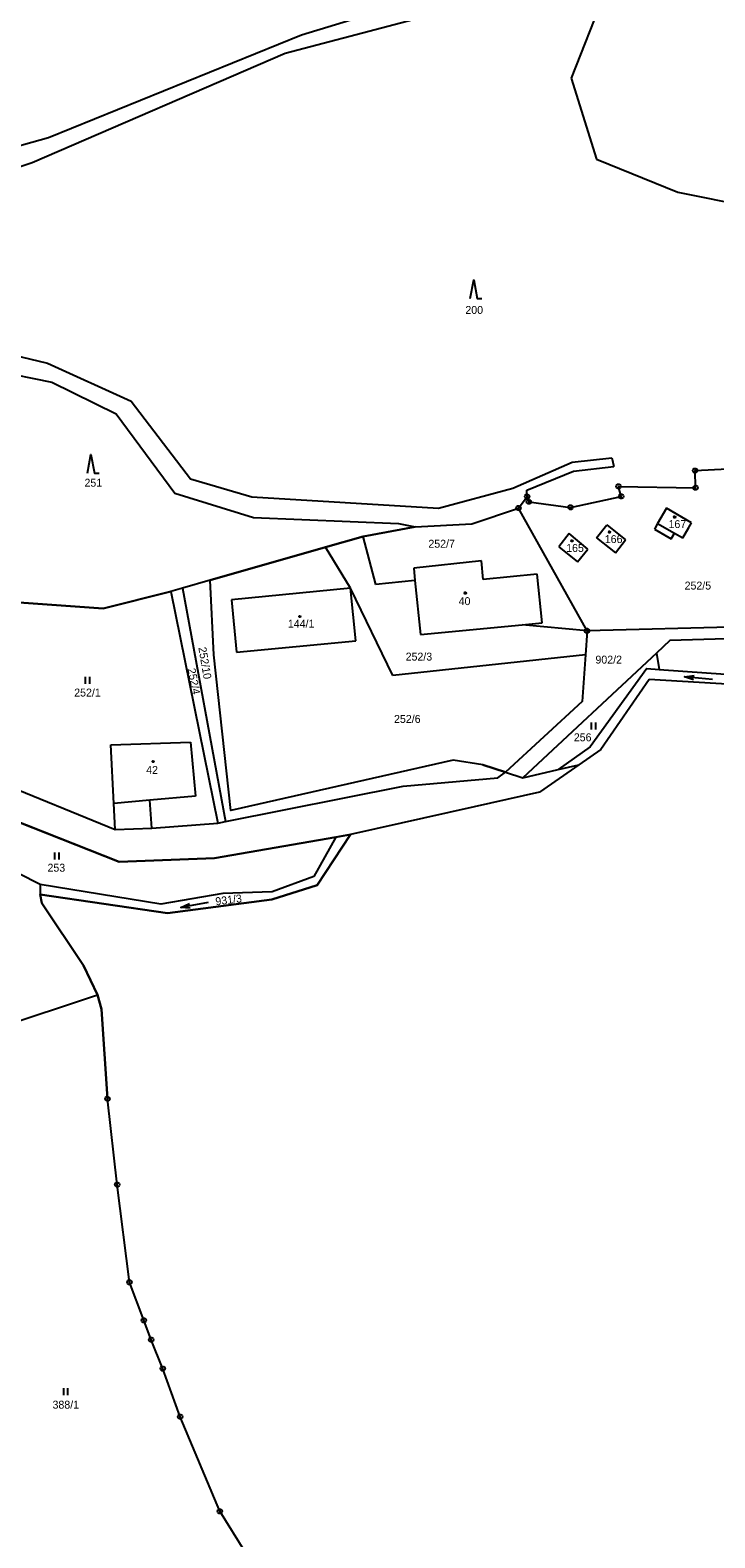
# Model space of a CAD drawing. Extents: x -580551 to -575069, y -1073031 to -1067931.
# Drawn here: x -577069.2 to -576922.3, y -1070091.5 to -1069768.1 of the extents above; entities that cross this region are included whole.
import ezdxf

# ---------------------------------------------------------------- set-up
doc = ezdxf.new("R2010")
doc.units = 0
for name, color, linetype in [('Druh pozemku', 7, 'Continuous'), ('Geodetické body', 7, 'Continuous'), ('Katastrální hranice', 7, 'Continuous'), ('Parcela', 7, 'Continuous'), ('Parcelní číslo', 7, 'Continuous'), ('Parcelní číslo_stavba', 7, 'Continuous'), ('SR - hranice státu', 7, 'Continuous'), ('SR - vnitřní hranice', 7, 'Continuous'), ('Vnitřní kresba', 7, 'Continuous'), ('Vrstva 6', 7, 'Continuous')]:
    doc.layers.add(name, color=color, linetype=linetype)

msp = doc.modelspace()

# ---------------------------------------------------------------- linework, layer by layer
at = {"layer": 'Druh pozemku'}
for p, q in [((-577057.43, -1069906.84), (-577057.43, -1069908.34)), ((-577056.43, -1069908.34), (-577056.43, -1069906.84)), ((-576922.843, -1069907.4), (-576928.817, -1069906.84)), ((-576948.87, -1069916.65), (-576948.87, -1069918.15)), ((-576947.87, -1069918.15), (-576947.87, -1069916.65)), ((-577063.95, -1069944.52), (-577063.95, -1069946.02)), ((-577062.95, -1069946.02), (-577062.95, -1069944.52)), ((-577030.998, -1069955.278), (-577036.902, -1069956.342)), ((-577062.09, -1070059.4), (-577062.09, -1070060.9)), ((-577061.09, -1070060.9), (-577061.09, -1070059.4))]:
    msp.add_line(p, q, dxfattribs=at)
for points in [[(-576974.79, -1069825.67), (-576974.04, -1069821.67), (-576973.29, -1069825.67), (-576972.29, -1069825.67)], [(-577056.93, -1069863.15), (-577056.18, -1069859.15), (-577055.43, -1069863.15), (-577054.43, -1069863.15)], [(-576926.872, -1069907.524), (-576928.817, -1069906.84), (-576926.779, -1069906.529)], [(-577034.845, -1069956.48), (-577036.902, -1069956.342), (-577035.023, -1069955.495)]]:
    msp.add_lwpolyline(points, dxfattribs=at)
for points in [[(-576930.83, -1069872.42), (-576930.74, -1069872.57), (-576930.83, -1069872.72), (-576931.01, -1069872.72), (-576931.1, -1069872.57), (-576931.01, -1069872.42)], [(-576952.88, -1069877.5), (-576952.79, -1069877.65), (-576952.88, -1069877.8), (-576953.06, -1069877.8), (-576953.15, -1069877.65), (-576953.06, -1069877.5)], [(-576944.82, -1069875.63), (-576944.73, -1069875.78), (-576944.82, -1069875.93), (-576945, -1069875.93), (-576945.09, -1069875.78), (-576945, -1069875.63)], [(-576975.75, -1069888.71), (-576975.66, -1069888.86), (-576975.75, -1069889.01), (-576975.93, -1069889.01), (-576976.02, -1069888.86), (-576975.93, -1069888.71)], [(-577011.27, -1069893.78), (-577011.18, -1069893.93), (-577011.27, -1069894.08), (-577011.45, -1069894.08), (-577011.54, -1069893.93), (-577011.45, -1069893.78)], [(-577042.74, -1069924.85), (-577042.65, -1069925), (-577042.74, -1069925.15), (-577042.92, -1069925.15), (-577043.01, -1069925), (-577042.92, -1069924.85)]]:
    msp.add_lwpolyline(points, close=True, dxfattribs=at)
at = {"layer": 'Geodetické body'}
for p, q in [((-576926.68, -1069862.61), (-576926.44, -1069862.61)), ((-576962.71, -1069868.15), (-576962.47, -1069868.15)), ((-576943.1, -1069866), (-576942.86, -1069866)), ((-576942.52, -1069868.15), (-576942.28, -1069868.15)), ((-576926.57, -1069866.31), (-576926.33, -1069866.31)), ((-576964.57, -1069870.66), (-576964.33, -1069870.66)), ((-576962.35, -1069869.31), (-576962.11, -1069869.31)), ((-576953.38, -1069870.49), (-576953.14, -1069870.49)), ((-576949.86, -1069896.96), (-576949.62, -1069896.96)), ((-577052.75, -1069997.36), (-577052.51, -1069997.36)), ((-577050.64, -1070015.78), (-577050.4, -1070015.78)), ((-577048.03, -1070036.7), (-577047.79, -1070036.7)), ((-577044.94, -1070044.86), (-577044.7, -1070044.86)), ((-577043.37, -1070049.05), (-577043.13, -1070049.05)), ((-577040.89, -1070055.25), (-577040.65, -1070055.25)), ((-577037.13, -1070065.58), (-577036.89, -1070065.58)), ((-577028.64, -1070085.83), (-577028.4, -1070085.83))]:
    msp.add_line(p, q, dxfattribs=at)
for points in [[(-576926.41, -1069862.13), (-576926.16, -1069862.31), (-576926.06, -1069862.6), (-576926.16, -1069862.89), (-576926.41, -1069863.07), (-576926.72, -1069863.07), (-576926.97, -1069862.89), (-576927.07, -1069862.6), (-576926.97, -1069862.31), (-576926.72, -1069862.13)], [(-576962.44, -1069867.67), (-576962.19, -1069867.85), (-576962.09, -1069868.14), (-576962.19, -1069868.43), (-576962.44, -1069868.61), (-576962.75, -1069868.61), (-576963, -1069868.43), (-576963.1, -1069868.14), (-576963, -1069867.85), (-576962.75, -1069867.67)], [(-576942.83, -1069865.52), (-576942.58, -1069865.7), (-576942.48, -1069865.99), (-576942.58, -1069866.28), (-576942.83, -1069866.46), (-576943.14, -1069866.46), (-576943.39, -1069866.28), (-576943.49, -1069865.99), (-576943.39, -1069865.7), (-576943.14, -1069865.52)], [(-576942.25, -1069867.67), (-576942, -1069867.85), (-576941.9, -1069868.14), (-576942, -1069868.43), (-576942.25, -1069868.61), (-576942.56, -1069868.61), (-576942.81, -1069868.43), (-576942.91, -1069868.14), (-576942.81, -1069867.85), (-576942.56, -1069867.67)], [(-576926.3, -1069865.83), (-576926.05, -1069866.01), (-576925.95, -1069866.3), (-576926.05, -1069866.59), (-576926.3, -1069866.77), (-576926.61, -1069866.77), (-576926.86, -1069866.59), (-576926.96, -1069866.3), (-576926.86, -1069866.01), (-576926.61, -1069865.83)], [(-576964.3, -1069870.18), (-576964.05, -1069870.36), (-576963.95, -1069870.65), (-576964.05, -1069870.94), (-576964.3, -1069871.12), (-576964.61, -1069871.12), (-576964.86, -1069870.94), (-576964.96, -1069870.65), (-576964.86, -1069870.36), (-576964.61, -1069870.18)], [(-576962.08, -1069868.83), (-576961.83, -1069869.01), (-576961.73, -1069869.3), (-576961.83, -1069869.59), (-576962.08, -1069869.77), (-576962.39, -1069869.77), (-576962.64, -1069869.59), (-576962.74, -1069869.3), (-576962.64, -1069869.01), (-576962.39, -1069868.83)], [(-576953.11, -1069870.01), (-576952.86, -1069870.19), (-576952.76, -1069870.48), (-576952.86, -1069870.77), (-576953.11, -1069870.95), (-576953.42, -1069870.95), (-576953.67, -1069870.77), (-576953.77, -1069870.48), (-576953.67, -1069870.19), (-576953.42, -1069870.01)], [(-576949.59, -1069896.48), (-576949.34, -1069896.66), (-576949.24, -1069896.95), (-576949.34, -1069897.24), (-576949.59, -1069897.42), (-576949.9, -1069897.42), (-576950.15, -1069897.24), (-576950.25, -1069896.95), (-576950.15, -1069896.66), (-576949.9, -1069896.48)], [(-577052.48, -1069996.88), (-577052.23, -1069997.06), (-577052.13, -1069997.35), (-577052.23, -1069997.64), (-577052.48, -1069997.82), (-577052.79, -1069997.82), (-577053.04, -1069997.64), (-577053.14, -1069997.35), (-577053.04, -1069997.06), (-577052.79, -1069996.88)], [(-577050.37, -1070015.3), (-577050.12, -1070015.48), (-577050.02, -1070015.77), (-577050.12, -1070016.06), (-577050.37, -1070016.24), (-577050.68, -1070016.24), (-577050.93, -1070016.06), (-577051.03, -1070015.77), (-577050.93, -1070015.48), (-577050.68, -1070015.3)], [(-577047.76, -1070036.22), (-577047.51, -1070036.4), (-577047.41, -1070036.69), (-577047.51, -1070036.98), (-577047.76, -1070037.16), (-577048.07, -1070037.16), (-577048.32, -1070036.98), (-577048.42, -1070036.69), (-577048.32, -1070036.4), (-577048.07, -1070036.22)], [(-577044.67, -1070044.38), (-577044.42, -1070044.56), (-577044.32, -1070044.85), (-577044.42, -1070045.14), (-577044.67, -1070045.32), (-577044.98, -1070045.32), (-577045.23, -1070045.14), (-577045.33, -1070044.85), (-577045.23, -1070044.56), (-577044.98, -1070044.38)], [(-577043.1, -1070048.57), (-577042.85, -1070048.75), (-577042.75, -1070049.04), (-577042.85, -1070049.33), (-577043.1, -1070049.51), (-577043.41, -1070049.51), (-577043.66, -1070049.33), (-577043.76, -1070049.04), (-577043.66, -1070048.75), (-577043.41, -1070048.57)], [(-577040.62, -1070054.77), (-577040.37, -1070054.95), (-577040.27, -1070055.24), (-577040.37, -1070055.53), (-577040.62, -1070055.71), (-577040.93, -1070055.71), (-577041.18, -1070055.53), (-577041.28, -1070055.24), (-577041.18, -1070054.95), (-577040.93, -1070054.77)], [(-577036.86, -1070065.1), (-577036.61, -1070065.28), (-577036.51, -1070065.57), (-577036.61, -1070065.86), (-577036.86, -1070066.04), (-577037.17, -1070066.04), (-577037.42, -1070065.86), (-577037.52, -1070065.57), (-577037.42, -1070065.28), (-577037.17, -1070065.1)], [(-577028.37, -1070085.35), (-577028.12, -1070085.53), (-577028.02, -1070085.82), (-577028.12, -1070086.11), (-577028.37, -1070086.29), (-577028.68, -1070086.29), (-577028.93, -1070086.11), (-577029.03, -1070085.82), (-577028.93, -1070085.53), (-577028.68, -1070085.35)]]:
    msp.add_lwpolyline(points, close=True, dxfattribs=at)
at = {"layer": 'Katastrální hranice'}
for p, q in [((-576936.44, -1069907.45), (-576946.78, -1069922.44)), ((-576902.47, -1069909.45), (-576936.44, -1069907.45)), ((-576946.78, -1069922.44), (-576951.48, -1069925.7)), ((-576951.48, -1069925.7), (-576959.97, -1069931.59)), ((-576959.97, -1069931.59), (-576973.92, -1069934.75)), ((-576973.92, -1069934.75), (-577000.48, -1069940.66)), ((-577000.48, -1069940.66), (-577007.65, -1069951.52)), ((-577007.65, -1069951.52), (-577017.38, -1069954.6)), ((-577039.74, -1069957.53), (-577067.05, -1069953.57)), ((-577067.05, -1069953.57), (-577066.7, -1069955.43)), ((-577066.7, -1069955.43), (-577057.78, -1069968.74)), ((-577017.38, -1069954.6), (-577039.74, -1069957.53)), ((-577057.78, -1069968.74), (-577054.76, -1069975.04)), ((-577054.76, -1069975.04), (-577053.89, -1069978.15)), ((-577053.89, -1069978.15), (-577052.63, -1069997.36)), ((-577050.52, -1070015.78), (-577052.63, -1069997.36)), ((-577047.91, -1070036.7), (-577050.52, -1070015.78)), ((-577044.82, -1070044.86), (-577047.91, -1070036.7)), ((-577043.25, -1070049.05), (-577044.82, -1070044.86)), ((-577040.77, -1070055.25), (-577043.25, -1070049.05)), ((-577037.01, -1070065.58), (-577040.77, -1070055.25)), ((-577028.52, -1070085.83), (-577037.01, -1070065.58)), ((-577023.03, -1070094.68), (-577028.52, -1070085.83))]:
    msp.add_line(p, q, dxfattribs=at)
at = {"layer": 'Parcela'}
for p, q in [((-576944.69, -1069748.96), (-577011, -1069769.24)), ((-576943.71, -1069754.47), (-577014.5, -1069773.16)), ((-576943.71, -1069754.47), (-576953.12, -1069778.4)), ((-577011, -1069769.24), (-577065.27, -1069791.23)), ((-577014.5, -1069773.16), (-577068.75, -1069796.56)), ((-576953.12, -1069778.4), (-576947.74, -1069795.79)), ((-577065.27, -1069791.23), (-577099.61, -1069800.79)), ((-577068.75, -1069796.56), (-577096.37, -1069805.82)), ((-576947.74, -1069795.79), (-576930.27, -1069802.9)), ((-576930.27, -1069802.9), (-576890.62, -1069810.92)), ((-577084.11, -1069835.17), (-577065.48, -1069839.55)), ((-577082.96, -1069839.91), (-577064.57, -1069843.63)), ((-577065.48, -1069839.55), (-577047.56, -1069847.69)), ((-577064.57, -1069843.63), (-577050.77, -1069850.42)), ((-577047.56, -1069847.69), (-577034.81, -1069864.39)), ((-577050.77, -1069850.42), (-577038.16, -1069867.46)), ((-576965.63, -1069866.39), (-576952.96, -1069860.79)), ((-576952.96, -1069860.79), (-576944.41, -1069859.85)), ((-576952.63, -1069862.75), (-576943.96, -1069861.75)), ((-576944.41, -1069859.85), (-576943.96, -1069861.75)), ((-576926.56, -1069862.61), (-576916.84, -1069862.07)), ((-577034.81, -1069864.39), (-577021.65, -1069868.22)), ((-576962.63, -1069866.84), (-576952.63, -1069862.75)), ((-576926.45, -1069866.31), (-576926.56, -1069862.61)), ((-577038.16, -1069867.46), (-577021.28, -1069872.69)), ((-577021.65, -1069868.22), (-576981.62, -1069870.67)), ((-576981.62, -1069870.67), (-576965.63, -1069866.39)), ((-576964.45, -1069870.66), (-576962.59, -1069868.15)), ((-576962.59, -1069868.15), (-576962.63, -1069866.84)), ((-576962.59, -1069868.15), (-576962.23, -1069869.31)), ((-576953.26, -1069870.49), (-576942.4, -1069868.15)), ((-576942.4, -1069868.15), (-576942.98, -1069866)), ((-576942.98, -1069866), (-576926.45, -1069866.31)), ((-576974.48, -1069874.01), (-576964.45, -1069870.66)), ((-576949.74, -1069896.96), (-576964.45, -1069870.66)), ((-576962.23, -1069869.31), (-576953.26, -1069870.49)), ((-576932.67, -1069870.66), (-576934.59, -1069873.93)), ((-576927.31, -1069873.82), (-576932.67, -1069870.66)), ((-577021.28, -1069872.69), (-576990.21, -1069873.93)), ((-576986.63, -1069874.69), (-576997.76, -1069876.76)), ((-576990.21, -1069873.93), (-576986.63, -1069874.69)), ((-576986.63, -1069874.69), (-576974.48, -1069874.01)), ((-576947.7, -1069877.04), (-576945.49, -1069874.25)), ((-576945.49, -1069874.25), (-576941.45, -1069877.47)), ((-576934.59, -1069873.93), (-576935.29, -1069875.14)), ((-576929.22, -1069877.06), (-576927.89, -1069874.8)), ((-576927.89, -1069874.8), (-576927.31, -1069873.82)), ((-576997.76, -1069876.76), (-577005.86, -1069879.06)), ((-576995.04, -1069887.02), (-576997.76, -1069876.76)), ((-576953.56, -1069876.13), (-576955.81, -1069878.97)), ((-576949.55, -1069879.44), (-576953.56, -1069876.13)), ((-576947.7, -1069877.04), (-576943.66, -1069880.24)), ((-576943.66, -1069880.24), (-576941.45, -1069877.47)), ((-576935.29, -1069875.14), (-576931.69, -1069877.22)), ((-576931.69, -1069877.22), (-576931, -1069876.03)), ((-576931, -1069876.03), (-576929.22, -1069877.06)), ((-577005.86, -1069879.06), (-577030.61, -1069886.1)), ((-577000.5, -1069887.82), (-577005.86, -1069879.06)), ((-576955.81, -1069878.97), (-576951.79, -1069882.15)), ((-576951.79, -1069882.15), (-576949.55, -1069879.44)), ((-576972.39, -1069881.95), (-576986.91, -1069883.57)), ((-576986.91, -1069883.57), (-576986.65, -1069886.16)), ((-576972, -1069885.97), (-576972.39, -1069881.95)), ((-577036.54, -1069887.81), (-577039.02, -1069888.52)), ((-577030.61, -1069886.1), (-577036.54, -1069887.81)), ((-577029.78, -1069902.1), (-577030.61, -1069886.1)), ((-577000.5, -1069887.82), (-577026, -1069890.35)), ((-576991.42, -1069906.59), (-577000.5, -1069887.82)), ((-576999.33, -1069899.12), (-577000.5, -1069887.82)), ((-576986.65, -1069886.16), (-576995.04, -1069887.02)), ((-576986.65, -1069886.16), (-576985.5, -1069897.77)), ((-576960.44, -1069884.83), (-576972, -1069885.97)), ((-576959.37, -1069895.25), (-576960.44, -1069884.83)), ((-577053.57, -1069892.18), (-577073.55, -1069890.78)), ((-577039.02, -1069888.52), (-577053.57, -1069892.18)), ((-577039.02, -1069888.52), (-577028.97, -1069938.24)), ((-577026, -1069890.35), (-577024.94, -1069901.53)), ((-576985.5, -1069897.77), (-576963.65, -1069895.66)), ((-576963.65, -1069895.66), (-576959.37, -1069895.25)), ((-576949.74, -1069896.96), (-576963.65, -1069895.66)), ((-576949.74, -1069896.96), (-576950.1, -1069902.15)), ((-576916.3, -1069896.13), (-576949.74, -1069896.96)), ((-577024.94, -1069901.53), (-576999.33, -1069899.12)), ((-576931.95, -1069899.07), (-576934.85, -1069901.78)), ((-576911.76, -1069898.43), (-576931.95, -1069899.07)), ((-577026.16, -1069935.55), (-577029.78, -1069902.1)), ((-576950.1, -1069902.15), (-576991.42, -1069906.59)), ((-576934.85, -1069901.78), (-576963.49, -1069928.49)), ((-576950.1, -1069902.15), (-576950.79, -1069912.11)), ((-576934.85, -1069901.78), (-576934.29, -1069905.26)), ((-576936.94, -1069905.08), (-576949.05, -1069921.87)), ((-576936.94, -1069905.08), (-576934.29, -1069905.26)), ((-576934.29, -1069905.26), (-576902.79, -1069907.45)), ((-576950.79, -1069912.11), (-576967.23, -1069927.27)), ((-577050.1, -1069946.52), (-577112.01, -1069922.1)), ((-577051.92, -1069921.46), (-577034.83, -1069920.88)), ((-577051.24, -1069934.01), (-577051.92, -1069921.46)), ((-577034.83, -1069920.88), (-577033.74, -1069932.43)), ((-576949.05, -1069921.87), (-576955.92, -1069926.73)), ((-577083.84, -1069926.22), (-577050.94, -1069939.56)), ((-576978.45, -1069924.69), (-577026.16, -1069935.55)), ((-576972.1, -1069925.69), (-576978.45, -1069924.69)), ((-576972.1, -1069925.69), (-576967.23, -1069927.27)), ((-576963.49, -1069928.49), (-576955.92, -1069926.73)), ((-576955.92, -1069926.73), (-576951.48, -1069925.7)), ((-577067.04, -1069951.41), (-577115.27, -1069927.04)), ((-576989.21, -1069930.32), (-576968.9, -1069928.52)), ((-576968.9, -1069928.52), (-576967.23, -1069927.27)), ((-576967.23, -1069927.27), (-576963.49, -1069928.49)), ((-577033.74, -1069932.43), (-577043.55, -1069933.31)), ((-577043.12, -1069939.33), (-577043.55, -1069933.31)), ((-577027.29, -1069937.91), (-576989.21, -1069930.32)), ((-577050.94, -1069939.56), (-577051.24, -1069934.01)), ((-577050.94, -1069939.56), (-577043.12, -1069939.33)), ((-577043.12, -1069939.33), (-577028.97, -1069938.24)), ((-577028.97, -1069938.24), (-577027.29, -1069937.91)), ((-577003.65, -1069941.21), (-577029.68, -1069945.77)), ((-577003.65, -1069941.21), (-577008.37, -1069949.65)), ((-577000.48, -1069940.66), (-577003.65, -1069941.21)), ((-577029.68, -1069945.77), (-577050.1, -1069946.52)), ((-577067.04, -1069951.41), (-577067.05, -1069953.57)), ((-577041.19, -1069955.62), (-577067.04, -1069951.41)), ((-577008.37, -1069949.65), (-577017.31, -1069952.95)), ((-577027.88, -1069953.34), (-577041.19, -1069955.62)), ((-577017.31, -1069952.95), (-577027.88, -1069953.34)), ((-577082.98, -1069984.46), (-577054.76, -1069975.04))]:
    msp.add_line(p, q, dxfattribs=at)
at = {"layer": 'SR - hranice státu'}
for p, q in [((-577073.55, -1069890.78), (-577053.57, -1069892.18)), ((-577053.57, -1069892.18), (-577039.02, -1069888.52))]:
    msp.add_line(p, q, dxfattribs=at)
for points in [[(-576942.98, -1069866), (-576926.45, -1069866.31), (-576926.56, -1069862.61), (-576916.84, -1069862.07), (-576916.77, -1069866.51), (-576900.43, -1069867.8)], [(-577005.86, -1069879.06), (-576997.76, -1069876.76), (-576986.63, -1069874.69), (-576974.48, -1069874.01), (-576964.45, -1069870.66), (-576962.59, -1069868.15), (-576962.23, -1069869.31), (-576953.26, -1069870.49), (-576942.4, -1069868.15), (-576942.98, -1069866)], [(-577039.02, -1069888.52), (-577028.97, -1069938.24), (-577027.29, -1069937.91), (-576989.21, -1069930.32), (-576968.9, -1069928.52), (-576967.23, -1069927.27), (-576972.1, -1069925.69), (-576978.45, -1069924.69), (-577026.16, -1069935.55), (-577029.78, -1069902.1), (-577030.61, -1069886.1), (-577005.86, -1069879.06)], [(-577112.01, -1069922.1), (-577050.1, -1069946.52), (-577029.68, -1069945.77), (-577003.65, -1069941.21), (-577000.48, -1069940.66)]]:
    msp.add_lwpolyline(points, dxfattribs=at)
at = {"layer": 'SR - vnitřní hranice'}
msp.add_lwpolyline([(-577023.03, -1070094.68), (-577028.52, -1070085.83), (-577037.01, -1070065.58), (-577040.77, -1070055.25), (-577043.25, -1070049.05), (-577044.82, -1070044.86), (-577047.91, -1070036.7), (-577050.52, -1070015.78), (-577052.63, -1069997.36), (-577053.89, -1069978.15), (-577054.76, -1069975.04), (-577057.78, -1069968.74), (-577066.7, -1069955.43), (-577067.05, -1069953.57), (-577039.74, -1069957.53), (-577017.38, -1069954.6), (-577007.65, -1069951.52), (-577000.48, -1069940.66)], dxfattribs=at)
at = {"layer": 'Vnitřní kresba'}
for p, q in [((-576934.59, -1069873.93), (-576931, -1069876.03)), ((-577043.55, -1069933.31), (-577051.24, -1069934.01))]:
    msp.add_line(p, q, dxfattribs=at)
at = {"layer": 'Vrstva 6'}
msp.add_line((-577036.54, -1069887.81), (-577027.29, -1069937.91), dxfattribs=at)

# ---------------------------------------------------------------- texts
at = {"layer": 'Parcelní číslo'}
for s, p in [('200', (-576975.836, -1069829)), ('251', (-577057.554, -1069866.06)), ('252/7', (-576983.775, -1069879.15)), ('252/5', (-576928.802, -1069888.12)), ('252/3', (-576988.647, -1069903.36)), ('902/2', (-576947.933, -1069904.01)), ('252/1', (-577059.754, -1069911.07)), ('252/6', (-576991.141, -1069916.73)), ('256', (-576952.571, -1069920.67)), ('253', (-577065.487, -1069948.64)), ('388/1', (-577064.406, -1070063.82))]:
    msp.add_text(s, height=1.7, dxfattribs=at).set_placement(p)
for s, rotation, p in [('252/10', 279.71799, (-577033.125, -1069900.595)), ('252/4', 280.92121, (-577035.426, -1069905.167)), ('931/3', 7.10468, (-577029.354, -1069955.876))]:
    msp.add_text(s, height=1.7, rotation=rotation, dxfattribs=at).set_placement(p)
at = {"layer": 'Parcelní číslo_stavba'}
for s, p in [('167', (-576932.252, -1069874.93)), ('165', (-576954.209, -1069880.06)), ('166', (-576945.927, -1069878.15)), ('40', (-576977.28, -1069891.46)), ('144/1', (-577013.915, -1069896.3)), ('42', (-577044.321, -1069927.68))]:
    msp.add_text(s, height=1.7, dxfattribs=at).set_placement(p)

doc.saveas('drawing.dxf')
